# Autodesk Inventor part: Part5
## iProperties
Shininess: 64.0
Length Units: 11269
Angle Units: 11279
Time Units: 11290
Mass Units: 11283
Length Display Precision: 3
Angle Display Precision: 2
Compacted: True
Part Number: Part5
Document SubType Name: Modeling
Created: 2002-12
Designer: deepak
Density: 0.0
Volumn: 0.0
Area: 0.0
PropertySet Name: Model Information
Control State: 0
Master: False
Checked Out: False
Author: deepak
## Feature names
1. Extrusion1
2. Fillet1
